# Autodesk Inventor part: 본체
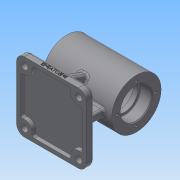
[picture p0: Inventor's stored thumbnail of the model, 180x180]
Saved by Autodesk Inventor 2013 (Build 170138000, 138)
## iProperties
Created: 2019-06
Part Number: 본체
Material: 일반
Document SubType Name: Modeling
Designer: Administrator
Density: 1 g/cm^3
Author: Administrator
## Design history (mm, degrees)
sketch "스케치1"
  geometry: L1 (0, 0)-(45, 0); L2 (45, 0)-(45, 32); L3 (45, 32)-(0, 32); L4 (0, 32)-(0, 0); L5 (45, 20)-(30, 20); L6 (30, 20)-(30, 17); L7 (30, 17)-(24, 17); L8 (24, 17)-(24, 25); L9 (24, 25)-(0, 25); 1 further point
  constraints: 18 end point, 5 perpendicular, 3 parallel, 2 point on line, 1 coincident, 1 horizontal
  dimensions: "d6" = 45 distance of L1.start L1.end; "d7" = 64 diameter of L3 L1; "d8" = 50 diameter of L9 L1; "d9" = 40 diameter of L5 L1; "d10" = 34 diameter of L7 L1; "d11" = 15 distance of L5.start L5.end; "d12" = 24 distance of L8.end L9.end
revolve "회전1" sketch "스케치1" stored, may be unused: angle "d13" = 90 deg
sketch "스케치2"
  geometry: C1 r 20 at (0, 0) reference; 1 further point
  constraints: 1 vertical alignment
  dimensions: "d14" = 25 distance of point (0, 25) C1.centre
hole "구멍1" sketch "스케치2" at (0, 25) diameter "d15" = 3.242; stored, may be unused: countersink angle "d19" = 90 deg, drill point angle "d21" = 118 deg; dims "d16" = 7, "d17" = 4, "d18" = 2, "d20" = 9
chamfer "모따기1" distance "d25" = 1; stored, may be unused: second distance "d26" = 2, angle "d27" = 45 deg
fillet "모깎기1" dims "d28" = 0.6
fillet "모깎기2" dims "d29" = 3
node "작업 평면2"
sketch "스케치3" dims "d35" = 10
  geometry: L1 (45, -45)-(-45, -45); L2 (-45, -45)-(-45, 45); L3 (-45, 45)-(45, 45); L4 (45, 45)-(45, -45); L5 (45, -45)-(-45, 45); L6 (-45, -45)-(45, 45); L7 (35, -5)-(-35, -5); L8 (-35, -5)-(-35, 5); L9 (-35, 5)-(35, 5); L10 (35, 5)-(35, -5); L11 (35, -5)-(-35, 5); L12 (-35, -5)-(35, 5); L13 (-40, 40)-(40, 40); L14 (40, 40)-(40, -40); L15 (40, -40)-(-40, -40); L16 (-40, -40)-(-40, 40); L17 (-40, -40)-(-30, -40); L18 (-40, -30)-(-40, -40); L19 (40, -40)-(30, -40); L20 (40, -30)-(40, -40); A1 r 10 centre (-35, 35) between (-40, 26.34) and (-26.34, 40); A2 r 10 centre (35, 35) between (26.34, 40) and (40, 26.34); 7 further points
  constraints: 40 end point, 8 midpoint, 6 parallel, 5 horizontal, 4 point on circle, 4 point on line, 3 coincident, 3 perpendicular, 2 centre point, 2 horizontal alignment, 1 vertical alignment
  dimensions: "d31" = 90 distance of L2.end L3.end; "d32" = 90 distance of L1.end L2.end; "d33" = 70 distance of L8.end L9.end; "d34" = 10 distance of L7.end L8.end; "d54" = 80 distance of L14.end L15.end; "d55" = 80 distance of L13.end L14.end; "d62" = 10 distance from line of point (-35, 35) L2; "d63" = 10 distance from line of point (-35, 35) L3; "d64" = 10 distance from line of point (35, 35) L4; "d68" = 10 radius of A1; "d70" = 10 radius of A2
extrude "돌출1" join sketch "스케치3" distance "d35" = 10; taper "d36" = 0 deg
extrude "돌출2" join sketch "스케치3" stored distance "d37" = 10; taper "d38" = 0 deg
node "작업 평면3"
sketch "스케치4"
  geometry: C1 r 5 at (0, 0); 1 further point
  constraints: 1 centre point, 1 coincident
  dimensions: "d40" = 10 diameter of C1
extrude "돌출3" join sketch "스케치4" stored distance "d41" = 10; taper "d42" = 0 deg
fillet "모깎기3" dims "d43" = 2
sketch "스케치5"
  geometry: L1 (-55, 35)-(-44.813, 31.292); L2 (-55, 45)-(-55, -45) reference; L3 (-65, 45)-(-55, 45) reference; 1 further point
  constraints: 2 end point, 1 point on line
  dimensions: "d44" = 110 deg angle of L1 L2; "d45" = 10 distance from line of L1.start L3
feature "리브1" sketch "스케치5" dims "d46" = 1, "d47" = 10, "d48" = 0, "d49" = 0, "d50" = 1, "d51" = 1
fillet "모깎기4" dims "d52" = 10
fillet "모깎기5" dims "d53" = 3
extrude "돌출4" cut sketch "스케치3" distance "d60" = 5; taper "d61" = 0 deg
extrude "돌출5" join sketch "스케치3" distance "d65" = 5; taper "d66" = 0 deg
extrude "돌출6" cut sketch "스케치3" distance "d75" = 5; taper "d76" = 0 deg
extrude "돌출7" join sketch "스케치3" distance "d77" = 5; taper "d78" = 0 deg
fillet "모깎기6" dims "d79" = 3
hole "구멍2" sketch "스케치3" diameter "d80" = 9; stored, may be unused: countersink angle "d84" = 90 deg, drill point angle "d86" = 0 deg; dims "d81" = 7, "d82" = 4, "d83" = 2, "d85" = 10
fillet "모깎기7" dims "d87" = 3
fillet "모깎기8" dims "d88" = 3
fillet "모깎기9" dims "d89" = 3
hole "구멍3" diameter "d92" = 4.917; stored, may be unused: countersink angle "d96" = 90 deg, drill point angle "d98" = 0 deg; dims "d90" = 10, "d91" = 10, "d93" = 7, "d94" = 4, "d95" = 2, "d97" = 10
sketch "스케치6"
  geometry: L1 (0, 0)-(-10, 0) reference; 2 further points
  constraints: 1 other
  dimensions: "d99" = 4 distance from line of point (35, 4) L1; "d100" = 45 horizontal distance of point (35, 4) L1.end
feature "엠보싱1" sketch "스케치6" dims "d6" = 45, "d7" = 64, "d8" = 50, "d9" = 40, "d10" = 34, "d11" = 15, "d12" = 24, "d101" = 0.5, "d102" = 0
node "솔리드1"
pattern_circular "원형 패턴1" dims angle "d23" = 360 deg
mirror "대칭1"
mirror "대칭2"
mirror "대칭3"
other parameters: "d30" = -65
